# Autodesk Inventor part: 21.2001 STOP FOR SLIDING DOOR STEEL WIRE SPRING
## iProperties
Created: 2007-05
Part Number: 21.2001 STOP FOR SLIDING DOOR STEEL WIRE SPRING
Document SubType Name: Modeling
Designer: Andy Moles
Material: Steel
Mass: 5.26165 g
Surface Area: 18.9118 cm^2
Volume: 0.670274 cm^3
Density: 7.85 g/cm^3
Author: Andy Moles
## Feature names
1. Base1
